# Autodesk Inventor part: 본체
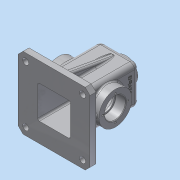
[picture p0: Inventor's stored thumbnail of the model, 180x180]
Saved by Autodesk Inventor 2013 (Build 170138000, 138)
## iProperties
Created: 2018-10
Part Number: 본체
Material: 알루미늄 6061
Document SubType Name: Modeling
Designer: Administrator
Density: 2.71 g/cm^3
Mass: 797.171 g
Surface Area: 899.499 cm^2
Volume: 294.159 cm^3
Author: Administrator
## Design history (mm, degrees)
sketch "스케치1"
  geometry: L1 (-32.5, -32.5)-(32.5, -32.5); L2 (32.5, -32.5)-(32.5, 32.5); L3 (32.5, 32.5)-(-32.5, 32.5); L4 (-32.5, 32.5)-(-32.5, -32.5); L5 (-32.5, -32.5)-(32.5, 32.5); L6 (32.5, -32.5)-(-32.5, 32.5); 1 further point
  constraints: 12 end point, 2 midpoint, 2 parallel, 1 horizontal, 1 perpendicular
  dimensions: "d0" = 65 distance of L3.end L2.end; "d1" = 65 distance of L2.end L1.end
extrude "돌출1" new body sketch "스케치1" stored distance "d2" = 110; taper "d3" = 0 deg
fillet "모깎기1" dims "d4" = 8
fillet "모깎기2" dims "d5" = 8
feature "쉘1" dims "d12" = 5
sketch "스케치4"
  geometry: C1 r 27.5 at (24.5, 55); 1 further point
  constraints: 1 centre point, 1 coincident
  dimensions: "d13" = 55 diameter of C1
extrude "돌출4" join sketch "스케치4" distance "d14" = 15; taper "d15" = 0 deg
sketch "스케치5"
  geometry: C1 r 27.5 at (24.5, 55); 1 further point
  constraints: 1 centre point, 1 coincident
  dimensions: "d16" = 55 diameter of C1
extrude "돌출5" join sketch "스케치5" distance "d17" = 15; taper "d18" = 0 deg
node "작업 평면1"
sketch "스케치10"
  geometry: C1 r 20 at (0, 0); 1 further point
  constraints: 1 centre point, 1 coincident
  dimensions: "d33" = 40 diameter of C1
extrude "돌출9" join sketch "스케치10" distance "d34" = 10; taper "d35" = 7 deg
hole "구멍1" diameter "d38" = 22.835; stored, may be unused: countersink angle "d42" = 90 deg, drill point angle "d44" = 118 deg; dims "d36" = 10, "d37" = 10, "d39" = 30, "d40" = 4, "d41" = 2, "d43" = 30
fillet "모깎기3" dims "d45" = 3
sketch "스케치11"
  geometry: C1 r 27.5 at (0, 0) reference; C2 r 17.5 at (0, 0)
  constraints: 1 centre point, 1 coincident
  dimensions: "d46" = 35 diameter of C2
extrude "돌출10" cut sketch "스케치11" distance "d47" = 17; taper "d48" = 0 deg
sketch "스케치12"
  geometry: C1 r 17.5 at (0, 0) reference; C2 r 15 at (0, 0)
  constraints: 1 centre point, 1 coincident
  dimensions: "d49" = 30 diameter of C2
extrude "돌출11" cut sketch "스케치12" distance "d50" = 3; taper "d51" = 0 deg
sketch "스케치13"
  geometry: C1 r 27.5 at (0, 0) reference; C2 r 17.5 at (0, 0)
  constraints: 1 centre point, 1 coincident
  dimensions: "d52" = 35 diameter of C2
extrude "돌출12" cut sketch "스케치13" distance "d53" = 17; taper "d54" = 0 deg
sketch "스케치14"
  geometry: C1 r 17.5 at (0, 0) reference; C2 r 15 at (0, 0)
  constraints: 1 centre point, 1 coincident
  dimensions: "d55" = 30 diameter of C2
extrude "돌출13" cut sketch "스케치14" distance "d56" = 3; taper "d57" = 0 deg
fillet "모깎기4" dims "d58" = 3
sketch "스케치15"
  geometry: L1 (24.5, 32.5)-(-24.5, 32.5) reference; L2 (-32.5, 24.5)-(-32.5, -24.5) reference; L3 (-24.5, -32.5)-(24.5, -32.5) reference; L4 (32.5, -24.5)-(32.5, 24.5) reference; L5 (-60, -60)-(60, -60); L6 (60, -60)-(60, 60); L7 (60, 60)-(-60, 60); L8 (-60, 60)-(-60, -60); L9 (-60, -60)-(60, 60); L10 (60, -60)-(-60, 60); L11 (27.5, 24.5)-(27.5, -24.5); L12 (24.5, -27.5)-(-24.5, -27.5); L13 (-27.5, -24.5)-(-27.5, 24.5); L14 (-24.5, 27.5)-(24.5, 27.5); A1 r 8 centre (24.5, 24.5) between (32.5, 24.5) and (24.5, 32.5) reference; A2 r 8 centre (-24.5, 24.5) between (-24.5, 32.5) and (-32.5, 24.5) reference; A3 r 8 centre (-24.5, -24.5) between (-32.5, -24.5) and (-24.5, -32.5) reference; A4 r 8 centre (24.5, -24.5) between (24.5, -32.5) and (32.5, -24.5) reference; A5 r 3 centre (24.5, 24.5) between (27.5, 24.5) and (24.5, 27.5); A6 r 3 centre (24.5, -24.5) between (24.5, -27.5) and (27.5, -24.5); A7 r 3 centre (-24.5, -24.5) between (-27.5, -24.5) and (-24.5, -27.5); A8 r 3 centre (-24.5, 24.5) between (-24.5, 27.5) and (-27.5, 24.5); 3 further points
  constraints: 20 end point, 8 point on circle, 4 centre point, 3 midpoint, 2 parallel, 1 coincident, 1 horizontal, 1 perpendicular, 7 other
  dimensions: "d59" = 120 distance of L7.end L6.end; "d60" = 120 distance of L6.end L5.end; "d61" = 5 distance between parallel lines of L4 L11
extrude "돌출14" join sketch "스케치15" distance "d62" = 10; taper "d63" = 0 deg
chamfer "모따기2" distance "d64" = 8; stored, may be unused: second distance "d65" = 2, angle "d66" = 45 deg
sketch "스케치16"
  geometry: C1 r 5 at (47.5, -47.5); C2 r 5 at (47.5, 47.5); C3 r 5 at (-47.5, -47.5); C4 r 5 at (-47.5, 47.5); 1 further point
  constraints: 4 centre point
  dimensions: "d67" = 10 diameter of C1; "d68" = 10 diameter of C2; "d69" = 47.5 horizontal distance of C1.centre point (0, 0); "d70" = 47.5 horizontal distance of C1.centre point (0, 0); "d71" = 47.5 horizontal distance of point (0, 0) C2.centre; "d72" = 47.5 horizontal distance of point (0, 0) C2.centre; "d73" = 10 diameter of C3; "d74" = 10 diameter of C4; "d75" = 47.5 horizontal distance of C4.centre point (0, 0); "d76" = 47.5 horizontal distance of C4.centre point (0, 0); "d77" = 47.5 horizontal distance of C3.centre point (0, 0); "d78" = 47.5 horizontal distance of C3.centre point (0, 0)
extrude "돌출15" cut sketch "스케치16" stored distance "d79" = 10; taper "d80" = 0 deg
sketch "스케치17"
  geometry: L1 (42.5, -27.5)-(42.5, -45); L2 (30.5, -17.5)-(47.5, -17.5) reference; L3 (47.5, -17.5)-(47.5, -27.5) reference; L4 (47.5, -27.5)-(35.5, -27.5) reference; L5 (32.5, -30.5)-(32.5, -45) reference; L6 (32.5, -45)-(60, -45) reference; L7 (60, -45)-(60, -55) reference; L8 (60, -55)-(27.5, -55) reference; L9 (27.5, -55)-(27.5, -15) reference; L10 (27.5, -15)-(30.5, -15) reference; L11 (30.5, -15)-(30.5, -17.5) reference; L12 (-47.5, -17.5)-(-30.5, -17.5) reference; L13 (-30.5, -17.5)-(-30.5, -15) reference; L14 (-30.5, -15)-(-27.5, -15) reference; L15 (-27.5, -15)-(-27.5, -55) reference; L16 (-27.5, -55)-(-60, -55) reference; L17 (-60, -55)-(-60, -45) reference; L18 (-60, -45)-(-32.5, -45) reference; L19 (-32.5, -45)-(-32.5, -30.5) reference; L20 (-35.5, -27.5)-(-47.5, -27.5) reference; L21 (-47.5, -27.5)-(-47.5, -17.5) reference; L22 (-27.5, 47)-(-27.5, 15) reference; L23 (-27.5, 15)-(-30.5, 15) reference; L24 (-30.5, 15)-(-30.5, 17.5) reference; L25 (-30.5, 17.5)-(-47.5, 17.5) reference; L26 (-47.5, 17.5)-(-47.5, 27.5) reference; L27 (-47.5, 27.5)-(-35.5, 27.5) reference; L28 (-32.5, 30.5)-(-32.5, 47) reference; L29 (-24.5, 55)-(-23.882, 55) reference; L30 (-20.904, 57.634)-(-20, 65) reference; L31 (-20, 65)-(-11.418, 65) reference; L32 (-11.418, 65)-(-11.418, 50) reference; L33 (-11.418, 50)-(-24.5, 50) reference; L34 (24.5, 50)-(11.418, 50) reference; L35 (11.418, 50)-(11.418, 65) reference; L36 (11.418, 65)-(20, 65) reference; L37 (20, 65)-(20.904, 57.634) reference; L38 (23.882, 55)-(24.5, 55) reference; L39 (32.5, 47)-(32.5, 30.5) reference; L40 (35.5, 27.5)-(47.5, 27.5) reference; L41 (47.5, 27.5)-(47.5, 17.5) reference; L42 (47.5, 17.5)-(30.5, 17.5) reference; L43 (30.5, 17.5)-(30.5, 15) reference; L44 (30.5, 15)-(27.5, 15) reference; L45 (27.5, 15)-(27.5, 47) reference; A1 r 3 centre (35.5, -30.5) between (35.5, -27.5) and (32.5, -30.5) reference; A2 r 3 centre (-35.5, -30.5) between (-32.5, -30.5) and (-35.5, -27.5) reference; A3 r 3 centre (-24.5, 47) between (-24.5, 50) and (-27.5, 47) reference; A4 r 3 centre (-35.5, 30.5) between (-35.5, 27.5) and (-32.5, 30.5) reference; A5 r 8 centre (-24.5, 47) between (-24.5, 55) and (-32.5, 47) reference; A6 r 3 centre (-23.882, 58) between (-23.882, 55) and (-20.904, 57.634) reference; A7 r 3 centre (24.5, 47) between (27.5, 47) and (24.5, 50) reference; A8 r 3 centre (23.882, 58) between (20.904, 57.634) and (23.882, 55) reference; A9 r 8 centre (24.5, 47) between (32.5, 47) and (24.5, 55) reference; A10 r 3 centre (35.5, 30.5) between (32.5, 30.5) and (35.5, 27.5) reference; 1 further point
  constraints: 2 end point, 2 point on line, 1 vertical
  dimensions: "d81" = 15 distance between parallel lines of L1 L9
feature "리브1" sketch "스케치17" dims "d83" = 1, "d84" = 6, "d85" = 0, "d86" = 0, "d87" = 1, "d88" = 1
sketch "스케치18"
  geometry: L1 (-2.933, -40.582)-(-45, -48); L2 (47, 27.5)-(-55, 27.5) reference; L3 (-55, 27.5)-(-55, 60) reference; L4 (-55, 60)-(-45, 60) reference; L5 (-45, 60)-(-45, 32.5) reference; L6 (-45, 32.5)-(47, 32.5) reference; L7 (55, 24.5)-(55, 23.882) reference; L8 (57.634, 20.904)-(65, 20) reference; L9 (65, 20)-(65, 11.418) reference; L10 (65, 11.418)-(50, 11.418) reference; L11 (50, 11.418)-(50, 24.5) reference; L12 (50, -24.5)-(50, -11.418) reference; L13 (50, -11.418)-(65, -11.418) reference; L14 (65, -11.418)-(65, -20) reference; L15 (65, -20)-(57.634, -20.904) reference; L16 (55, -23.882)-(55, -24.5) reference; L17 (47, -32.5)-(-45, -32.5) reference; L18 (-45, -32.5)-(-45, -60) reference; L19 (-45, -60)-(-55, -60) reference; L20 (-55, -60)-(-55, -27.5) reference; L21 (-55, -27.5)-(47, -27.5) reference; A1 r 3 centre (47, 24.5) between (50, 24.5) and (47, 27.5) reference; A2 r 8 centre (47, 24.5) between (55, 24.5) and (47, 32.5) reference; A3 r 3 centre (58, 23.882) between (55, 23.882) and (57.634, 20.904) reference; A4 r 3 centre (47, -24.5) between (47, -27.5) and (50, -24.5) reference; A5 r 3 centre (58, -23.882) between (57.634, -20.904) and (55, -23.882) reference; A6 r 8 centre (47, -24.5) between (47, -32.5) and (55, -24.5) reference; 1 further point
  constraints: 2 end point, 1 point on line
  dimensions: "d89" = 12 distance from line of L19 L1.end; "d90" = 10 deg angle of L19 L1
feature "리브2" sketch "스케치18" dims "d91" = 1, "d92" = 10, "d93" = 0, "d94" = 0, "d95" = 1, "d96" = 1
fillet "모깎기5" dims "d97" = 3
fillet "모깎기6" dims "d98" = 3
chamfer "모따기3" distance "d99" = 1; stored, may be unused: second distance "d100" = 2, angle "d101" = 45 deg
fillet "모깎기7" dims "d102" = 0.3
sketch "스케치19"
  geometry: L1 (0, 0)-(0, 21); C1 r 27.5 at (0, 0) reference; 1 further point
  constraints: 2 coincident, 2 end point, 1 vertical
  dimensions: "d103" = 21 distance of L1.start L1.end
hole "구멍2" sketch "스케치19" at (0, 21) diameter "d104" = 3.242; stored, may be unused: countersink angle "d108" = 90 deg, drill point angle "d110" = 118 deg; dims "d105" = 8, "d106" = 4, "d107" = 2, "d109" = 10
sketch "스케치20"
  geometry: L1 (-8, 0)-(-8, -92) reference; L2 (4.5, 18)-(44.5, 18) reference; 1 further point
  constraints: 1 other
  dimensions: "d114" = 32.5 distance from line of point (24.5, -8) L1; "d115" = 26 distance from line of point (24.5, -8) L2
feature "엠보싱1" sketch "스케치20" dims "d116" = 0.5, "d117" = 0
fillet "모깎기8" dims "d118" = 3
fillet "모깎기9" dims "d119" = 3
fillet "모깎기10" dims "d120" = 1
chamfer "모따기4" distance "d121" = 1; stored, may be unused: second distance "d122" = 2, angle "d123" = 45 deg
node "솔리드1"
mirror "대칭1"
mirror "대칭2"
pattern_circular "원형 패턴1" dims angle "d112" = 360 deg
mirror "대칭3"
node "절단 모서리 투영1"
node "절단 모서리 투영2"
other parameters: "d32" = 65
